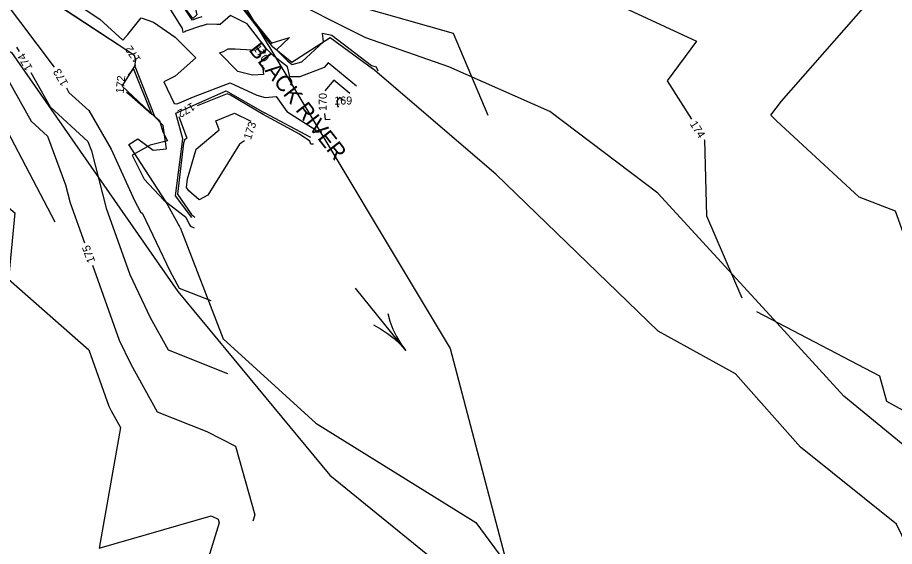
# Model space of a CAD drawing. Extents: x 2086416 to 2115205, y 575507 to 632762.
# Drawn here: x 2111557.3 to 2111776.5, y 581467.3 to 581599.4 of the extents above; entities that cross this region are included whole.
import ezdxf

# ---------------------------------------------------------------- set-up
doc = ezdxf.new("R2010")
doc.units = 0
for name, color, linetype in [('DTM Contours Major', 7, 'Continuous'), ('DTM Contours Major Text', 7, 'Continuous'), ('DTM Contours Minor', 7, 'Continuous'), ('DTM Contours Minor Text', 7, 'Continuous'), ('Exist Hydro River Flow Arrow CELL', 7, 'Continuous'), ('Exist Hydro Stream or Body of Water', 7, 'Continuous'), ('Exist Hydro Stream or Body of Water Text', 7, 'Continuous'), ('Exist Hydrographic Stream Bed', 7, 'Continuous'), ('Exist Vegetation Woods Line', 7, 'Continuous')]:
    doc.layers.add(name, color=color, linetype=linetype)

msp = doc.modelspace()

# ---------------------------------------------------------------- linework, layer by layer
at = {"layer": 'DTM Contours Major'}
for points in [[(2111534.94, 581633.7), (2111534.95, 581633.69), (2111540.69, 581621.59), (2111540.75, 581620.7), (2111543.07, 581605.02), (2111543.15, 581604.73), (2111546.21, 581598.92), (2111547.25, 581597.53), (2111560.71, 581573.54), (2111564.82, 581569.8), (2111569.33, 581557.68), (2111570.48, 581553.11), (2111574.03, 581543.19)], [(2111780.53, 581536.2), (2111779.91, 581542.21), (2111776.72, 581551.05), (2111767.61, 581554.53), (2111746.99, 581573.66), (2111745.59, 581575.02), (2111748.2, 581578.53), (2111769.31, 581602.49), (2111766.72, 581604.09), (2111762.55, 581607.47)], [(2111612.41, 581585.98), (2111607.79, 581590.61), (2111608.83, 581590.91), (2111609.95, 581591.62), (2111611.71, 581591.58), (2111615.79, 581591.34)], [(2111618.56, 581587.48), (2111618.79, 581585.22), (2111616.06, 581585), (2111612.41, 581585.98)], [(2111640.37, 581580.48), (2111636.37, 581583.8), (2111634.08, 581581.09)], [(2111634.02, 581575.42), (2111634.23, 581573.95), (2111635.48, 581574.08)], [(2111576.05, 581537.54), (2111582.75, 581518.81), (2111585.61, 581512.82), (2111592.18, 581500.96), (2111604.59, 581496.05), (2111611.81, 581492.33), (2111616.64, 581475.22), (2111616.16, 581473.64)]]:
    msp.add_lwpolyline(points, dxfattribs=at)
at = {"layer": 'DTM Contours Minor'}
for points in [[(2111589.24, 581620.71), (2111589.88, 581619.92), (2111590.86, 581618.93), (2111592.4, 581618.49), (2111599.33, 581615.1), (2111605.37, 581623.89), (2111605.71, 581625.53), (2111604.66, 581629.9), (2111612.58, 581630.28), (2111613.26, 581630.39), (2111619.38, 581630.75), (2111621.02, 581630.79), (2111642.89, 581633.66), (2111647.2, 581633.15), (2111648.46, 581631.54), (2111653.2, 581633.04), (2111670.86, 581631.97), (2111682.2, 581631.35), (2111685.06, 581615.46), (2111702.13, 581615.46), (2111706.66, 581602.93), (2111726.97, 581593.52), (2111719.65, 581583.63), (2111725.71, 581574.01)], [(2111577.85, 581632.76), (2111579.38, 581631.77), (2111585.59, 581622.88), (2111586.9, 581621.52), (2111588.77, 581619.19), (2111592.83, 581615.07), (2111599.25, 581613.25), (2111610.21, 581607.89), (2111612.26, 581606.57), (2111617.7, 581603.71), (2111619.12, 581601.94), (2111619.52, 581603.35), (2111619.22, 581603.58), (2111621.46, 581611.66), (2111622.11, 581614.01), (2111639.99, 581603.54), (2111640.81, 581603.36), (2111642.08, 581602.39), (2111666.16, 581595.53), (2111674.85, 581575.03)], [(2111549.08, 581629.05), (2111561.22, 581607.23), (2111561.71, 581606.42), (2111583.6, 581591.95)], [(2111554.71, 581624.02), (2111564.46, 581607.91), (2111577.89, 581599.03), (2111583.64, 581593.74), (2111584.9, 581595.2), (2111588.2, 581599.36), (2111591.32, 581598.31), (2111596.72, 581594.56), (2111601.88, 581589.39), (2111596.72, 581584.75), (2111593.84, 581583.38), (2111596.47, 581577.94), (2111597.16, 581577.87), (2111597.78, 581578.11), (2111601.3, 581579.62), (2111610.43, 581583.11), (2111617.16, 581580.01), (2111619.2, 581579.46), (2111621.97, 581579.69), (2111624.61, 581575.97), (2111631.97, 581571.27), (2111632.13, 581570.83), (2111633.37, 581570.96)], [(2111642, 581582.26), (2111634.94, 581588.12), (2111633.95, 581586.96), (2111627.89, 581584.61), (2111625.34, 581584.6), (2111624.75, 581587.14), (2111621.39, 581589.78), (2111619.57, 581591.62), (2111614.67, 581597.85), (2111610.55, 581599.98), (2111607.93, 581597.67), (2111607.12, 581597.71), (2111604.69, 581597.77), (2111603.18, 581597.28), (2111603.05, 581597.24), (2111599.38, 581596.01), (2111599.14, 581595.86), (2111598.69, 581595.73), (2111598.53, 581596.66), (2111585.91, 581617.09)], [(2111596.14, 581605.98), (2111600.86, 581598.82), (2111601.33, 581598.98), (2111602.4, 581599.34), (2111603.42, 581599.67)], [(2111553.76, 581604.05), (2111566.51, 581587.07)], [(2111611.76, 581604.31), (2111620.89, 581592.97), (2111620.93, 581593.1), (2111625.25, 581594.41), (2111622.03, 581591.39), (2111624.75, 581588.65), (2111625.98, 581587.68), (2111628.35, 581588.4), (2111633.8, 581593.35), (2111633.55, 581595.53), (2111635.83, 581595.02), (2111645.81, 581587.47), (2111646.98, 581587.13), (2111647.4, 581586.14)], [(2111557.09, 581592.02), (2111557.69, 581590.96)], [(2111586.68, 581587.63), (2111586.69, 581587.52), (2111586.67, 581587.29), (2111591.57, 581574.78), (2111591.61, 581574.7), (2111591.64, 581574.7), (2111592.77, 581573.73), (2111593.64, 581570.85), (2111594.79, 581568.61), (2111590.43, 581567.52), (2111585.93, 581565.06), (2111588.98, 581559.07), (2111593.91, 581553.81), (2111599, 581549.88), (2111599.4, 581549.59), (2111600.23, 581547.84), (2111600.52, 581547.32), (2111601.48, 581546.94)], [(2111560.62, 581585.72), (2111565.44, 581577.12), (2111574.93, 581568.49), (2111575.82, 581566.12), (2111579.43, 581551.8), (2111585.36, 581535.23), (2111590.48, 581524.5), (2111594.96, 581516.42), (2111609.82, 581510.54)], [(2111590.91, 581575.33), (2111586.27, 581586.68), (2111584.99, 581585.04)], [(2111569.52, 581581.89), (2111570.18, 581580.71), (2111575.13, 581576.21), (2111580.7, 581566.52), (2111586.55, 581553.77), (2111588.02, 581550.88), (2111588.51, 581550.52), (2111595.36, 581536.17), (2111597.74, 581531.87), (2111605.65, 581528.74)], [(2111584.58, 581580.78), (2111585.3, 581580.18), (2111590.91, 581575.33)], [(2111631.25, 581567.84), (2111630.64, 581567.77), (2111630.35, 581568.58), (2111627.82, 581570.29), (2111618.68, 581575.23), (2111610.55, 581580), (2111609.72, 581580.4), (2111602.22, 581577.39)], [(2111638.74, 581578.7), (2111637.8, 581579.48), (2111637.09, 581578.64), (2111637.3, 581577.17), (2111637.6, 581577.2)], [(2111597.64, 581574.71), (2111599.59, 581569.33), (2111599.01, 581568.84), (2111598.78, 581568.09), (2111597.29, 581555.28), (2111600.81, 581550.27), (2111601.6, 581549.57)], [(2111599.54, 581557), (2111599.79, 581559.16), (2111601.98, 581566.57), (2111607.71, 581571.38), (2111606.88, 581573.67), (2111611.5, 581575.52), (2111615.66, 581573.56)], [(2111614, 581568.6), (2111612.79, 581567.81), (2111604.84, 581555.04), (2111602.67, 581553.89), (2111600.13, 581556.16), (2111599.54, 581557)], [(2111728.9, 581568.93), (2111728.98, 581568.81), (2111729.5, 581549.93), (2111738.35, 581529.42)], [(2111549.42, 581565.48), (2111549.3, 581556.75), (2111556.68, 581550.67), (2111555.04, 581534.11), (2111575.11, 581516.45), (2111580.14, 581502.39), (2111580.74, 581501.15), (2111583.03, 581497), (2111577.68, 581466.9), (2111605.74, 581475), (2111607.43, 581474.14), (2111607.69, 581473.21), (2111591.9, 581421.84), (2111590.92, 581419.37), (2111591.04, 581419.17), (2111590.97, 581419.11)], [(2111795.57, 581491.95), (2111774.6, 581503.54), (2111772.79, 581509.85), (2111742.06, 581525.95)]]:
    msp.add_lwpolyline(points, dxfattribs=at)
at = {"layer": 'Exist Hydro River Flow Arrow CELL'}
for p, q in [((2111654.32, 581516.29), (2111641.77, 581531.86)), ((2111648.04, 581524.08), (2111648.04, 581524.08)), ((2111649.82, 581525.51), (2111650.4, 581523.55)), ((2111650.4, 581523.55), (2111651.14, 581521.61)), ((2111646.26, 581522.64), (2111648.06, 581521.67)), ((2111648.06, 581521.67), (2111649.8, 581520.53)), ((2111651.14, 581521.61), (2111652.05, 581519.73)), ((2111649.8, 581520.53), (2111651.44, 581519.24)), ((2111651.44, 581519.24), (2111652.97, 581517.84)), ((2111652.05, 581519.73), (2111653.09, 581517.93)), ((2111652.97, 581517.84), (2111654.32, 581516.29)), ((2111653.09, 581517.93), (2111654.32, 581516.29))]:
    msp.add_line(p, q, dxfattribs=at)
at = {"layer": 'Exist Hydro Stream or Body of Water'}
msp.add_line((2111630.63, 581569.49), (2111619.04, 581575.64), dxfattribs=at)
for points in [[(2111591.59, 581574.69), (2111583.51, 581582.32), (2111586.65, 581587.28), (2111586.9, 581588.76), (2111586.51, 581589.98), (2111561.57, 581606.34), (2111549, 581629.07), (2111542.47, 581641.26), (2111541.35, 581641.18), (2111528.82, 581652.89), (2111524.36, 581663.91), (2111523.31, 581667.75), (2111502.68, 581682.78), (2111481.94, 581698.46), (2111468.58, 581724.28), (2111463, 581737.48)], [(2111621.04, 581592.2), (2111611.64, 581604.33), (2111605.91, 581608.14), (2111600.48, 581607.01), (2111602.12, 581600.1), (2111601.11, 581599.2), (2111587.78, 581617.38), (2111576.69, 581633.34), (2111571.48, 581641.08), (2111570.64, 581641.03), (2111569.87, 581645.92), (2111561.21, 581659.64), (2111560.4, 581669.08), (2111561.77, 581674.66), (2111567.14, 581693.15), (2111571.77, 581696.53), (2111557.1, 581714.2)], [(2111621.04, 581592.2), (2111625.87, 581588.27), (2111635.48, 581594.43), (2111646, 581586.7)], [(2111785.01, 581456.38), (2111776.98, 581472.85), (2111753.02, 581492.1), (2111736.76, 581510.47), (2111717.38, 581521.12), (2111676.84, 581560.27), (2111646, 581586.7)], [(2111600.9, 581549.46), (2111596.8, 581554.91), (2111598.67, 581569.1), (2111596.9, 581575.53), (2111609.44, 581581.15), (2111619.04, 581575.64)], [(2111597.94, 581546.96), (2111594.36, 581553.52), (2111585.17, 581567.74), (2111587.38, 581569.17), (2111591.18, 581566.27), (2111594.55, 581566.67), (2111593.73, 581572.44), (2111591.59, 581574.69)], [(2111597.94, 581546.96), (2111608.71, 581519.2), (2111631.83, 581498.07), (2111671.82, 581473.29), (2111688.43, 581450.85), (2111710.78, 581426.78), (2111742.36, 581409.74), (2111754.48, 581398.89), (2111760.49, 581379.8)]]:
    msp.add_lwpolyline(points, dxfattribs=at)
at = {"layer": 'Exist Hydrographic Stream Bed'}
msp.add_lwpolyline([(2112129.65, 582477.71), (2111835.9, 582368.96), (2111727.15, 582231.15), (2111672.65, 582129.59), (2111610.9, 582009.96), (2111585.65, 581897.53), (2111574.65, 581806.9), (2111574.65, 581727.08), (2111582.9, 581679.52), (2111589.15, 581643.7), (2111621.9, 581589.33), (2111665.4, 581516.77), (2111701.65, 581379.01), (2111737.9, 581248.45), (2111785.15, 581103.39)], dxfattribs=at)
at = {"layer": 'Exist Vegetation Woods Line'}
for points in [[(2111779.57, 581491.97), (2111763.79, 581504.85), (2111745.34, 581525.06), (2111717.3, 581555.59), (2111690.35, 581575.95), (2111665.09, 581587.14), (2111644.35, 581594.34), (2111622.46, 581605.4), (2111614.18, 581617.92), (2111615.41, 581630.25), (2111644.69, 581636.02), (2111711.67, 581643.9), (2111763.23, 581655.57), (2111785.51, 581656)], [(2111257.87, 581581.4), (2111333.1, 581590.97), (2111406.18, 581600.07), (2111473.94, 581614.42), (2111501.63, 581613.42), (2111525.04, 581604.65), (2111555.79, 581590.73), (2111597.41, 581531.02), (2111635.4, 581485.12), (2111692.38, 581438.81), (2111736.92, 581397.7), (2111757.96, 581379.06)], [(2111566.76, 581548.29), (2111551.99, 581576.31), (2111385.4, 581583.05), (2111297.09, 581569.27), (2111253.55, 581562.72), (2111242.01, 581577.17), (2111257.87, 581581.4)]]:
    msp.add_lwpolyline(points, dxfattribs=at)

# ---------------------------------------------------------------- texts
at = {"layer": 'DTM Contours Major Text'}
for s, rotation, p in [('170', 305.7255, (2111616.12, 581591.73)), ('170', 89.445, (2111634.57, 581576.1)), ('175', 109.6834, (2111576.75, 581538.56))]:
    msp.add_text(s, height=2, rotation=rotation, dxfattribs=at).set_placement(p)
at = {"layer": 'DTM Contours Minor Text'}
for s, rotation, p in [('172', 125.4721, (2111588.24, 581589.02)), ('174', 119.2876, (2111561.14, 581586.84)), ('173', 120.1544, (2111570.06, 581583.04)), ('172', 84.6087, (2111583.82, 581580.4)), ('172', 210.2842, (2111600.9, 581578.28)), ('173', 71.5054, (2111615.62, 581568.76)), ('174', 302.1749, (2111725.25, 581572.86))]:
    msp.add_text(s, height=2, rotation=rotation, dxfattribs=at).set_placement(p)
msp.add_text('169', height=2, dxfattribs=at).set_placement((2111636.48, 581577.7))
at = {"layer": 'Exist Hydro Stream or Body of Water Text'}
msp.add_text('BLACK RIVER', height=4, rotation=307.9408, dxfattribs=at).set_placement((2111614.94, 581591.33))

doc.saveas('drawing.dxf')
